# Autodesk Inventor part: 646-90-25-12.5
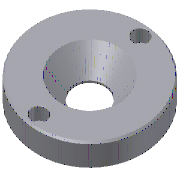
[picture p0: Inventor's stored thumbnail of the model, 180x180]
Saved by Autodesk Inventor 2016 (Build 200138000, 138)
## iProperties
Created: 2015-02
Part Number: 646-90-25-12.5
Material: ANFOR XC 38 TS
Description: Locating Ring
Document SubType Name: Modeling
Designer: Sandeep
Standard Revision: 1
Manufacturer: RABOURDIN
Language: en-US
Size Designation: 646-90-25-12.5
Categories: <MemberInstance><Categories><Category DisplayName="Mold" InternalName="349578f2-f4d4-4954-8c09-8e99297a61c0" Mnemonic="MOLD"><Category DisplayName="Locatings" I
Density: 7.845 g/cm^3
Appearance: Default
IsCustomPart: 1
Author: Sandeep
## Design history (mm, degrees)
sketch "Sketch1"
  geometry: L1 (0, -2.5)-(0, 15) reference; L2 (24, 12.5)-(12.5, 1); L3 (12.5, 1)-(12.5, 0); L4 (12.5, 0)-(45, 0); L5 (45, 0)-(45, 12.5); L6 (45, 12.5)-(24, 12.5); 1 further point
  constraints: 10 end point, 2 horizontal, 2 vertical, 1 point on line
  dimensions: "d0" = 45 deg angle of L1 L2; "d1" = 25 diameter of L3 L1 (= D2); "d2" = 90 diameter of L5 L1 (= D1); "d3" = 12.5 distance between parallel lines of L4 L6 (= A_); "d4" = 1 distance from line of L2.end L4 (= C_)
revolve "Revolution1" sketch "Sketch1" stored, may be unused: angle "d5" = 90 deg
sketch "Sketch2"
  geometry: 3 further points
  constraints: 2 vertical alignment
  dimensions: "d29" = 37 distance of point (0, 0) point (0, 37); "d30" = 37 distance of point (0, -37) point (0, 0)
hole "Hole1" sketch "Sketch2" diameter "d7" = 7; stored, may be unused: countersink angle "d11" = 90 deg, drill point angle "d13" = 0 deg; dims "d8" = 6, "d9" = 11, "d10" = 7, "d12" = 12.5 (= A_)
hole "Hole2" sketch "Sketch2" diameter "d31" = 7; stored, may be unused: countersink angle "d35" = 90 deg, drill point angle "d37" = 0 deg; dims "d32" = 6, "d33" = 11, "d34" = 7, "d36" = 12.5 (= A_)
chamfer "Chamfer1" distance "d14" = 1; stored, may be unused: second distance "d15" = 2, angle "d16" = 45 deg
chamfer "Chamfer2" distance "d17" = 0.5; stored, may be unused: second distance "d18" = 2, angle "d19" = 45 deg
chamfer "Chamfer3" distance "d20" = 0.3; stored, may be unused: second distance "d21" = 2, angle "d22" = 45 deg
sketch "Sketch3"
  geometry: L1 (0, -2.5)-(0, 15) reference; L2 (0, 0)-(45, 0); L3 (45, 0)-(45, 12.5); L4 (45, 12.5)-(0, 12.5); L5 (0, 12.5)-(0, 0)
  constraints: 8 end point, 2 parallel, 1 horizontal, 1 perpendicular
  dimensions: "d23" = 90 diameter of L3 L1 (= D1_CS); "d24" = 12.5 distance between parallel lines of L2 L4 (= A_CS)
feature "RevolutionSrf1" sketch "Sketch3" dims angle "d25" = 90 deg
body "Solid1"
body "Srf1"
other parameters: "D1" = 90 [user parameter; used in 1 equation term], "D2" = 25 [user parameter; used in 1 equation term], "A_" = 12.5 [user parameter; used in 3 equation terms], "C_" = 1 [user parameter; used in 1 equation term], "D1_CS" = 90 [user parameter; used in 1 equation term], "A_CS" = 12.5 [user parameter; used in 1 equation term], "d26" = 0, "d27" = 0, "d28" = 0
